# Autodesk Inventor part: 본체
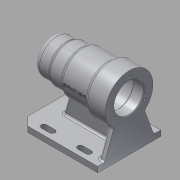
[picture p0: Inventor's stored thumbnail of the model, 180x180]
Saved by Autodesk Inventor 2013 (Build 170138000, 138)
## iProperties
Created: 2017-09
Part Number: 본체
Material: 알루미늄 6061
Document SubType Name: Modeling
Designer: Administrator
Density: 2.71 g/cm^3
Mass: 698.341 g
Surface Area: 709.394 cm^2
Volume: 257.691 cm^3
Author: Administrator
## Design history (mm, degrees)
sketch "스케치1"
  geometry: L1 (0, 0)-(-112, 0); L2 (-112, 22)-(-112, 34); L3 (-112, 34)-(-87, 34); L4 (-84, 31)-(-84, 30); L5 (-81.343, 30)-(-47.196, 30); L6 (-45, 30)-(-45, 30); L7 (-42, 27)-(-26.472, 27); L8 (-25, 27)-(-25, 28); L9 (-22, 25)-(-9, 25); L10 (0, 16)-(0, 0); L11 (-111, 21)-(-97, 21); L12 (-97, 21)-(-97, 21); L13 (-94, 24)-(-46, 24); L14 (-43, 21)-(-43, 21); L15 (-43, 21)-(-31.3, 21); L16 (-31, 20.7)-(-31, 17.5); L17 (-31, 17.5)-(-13.3, 17.5); L18 (-13, 17.2)-(-13, 16); L19 (-13, 16)-(-9.3, 16); L20 (-9, 15.7)-(-9, 10.5); L21 (-9, 10.5)-(-9, 10.5); L22 (-6, 7.5)-(-6, 0); L23 (-112, 22)-(-111, 21); A1 r 3 centre (-22, 28) between (-24.236, 26) and (-22, 25); A2 r 3 centre (-26.472, 24) between (-24.236, 26) and (-26.472, 27); A3 r 3 centre (-42, 30) between (-44.598, 28.5) and (-42, 27); A4 r 3 centre (-47.196, 27) between (-44.598, 28.5) and (-47.196, 30); A5 r 3 centre (-87, 31) between (-84.172, 32) and (-87, 34); A6 r 3 centre (-81.343, 33) between (-84.172, 32) and (-81.343, 30); A7 r 3 centre (-9, 7.5) between (-6, 7.5) and (-9, 10.5); A8 r 0.3 centre (-9.3, 15.7) between (-9, 15.7) and (-9.3, 16); A9 r 0.3 centre (-13.3, 17.2) between (-13, 17.2) and (-13.3, 17.5); A10 r 0.3 centre (-31.3, 20.7) between (-31, 20.7) and (-31.3, 21); A11 r 3 centre (-46, 21) between (-43, 21) and (-46, 24); A12 r 3 centre (-94, 21) between (-94, 24) and (-97, 21); A13 r 9 centre (-9, 16) between (0, 16) and (-9, 25); 9 further points
  constraints: 46 end point, 29 point on circle, 26 tangent, 23 point on line, 15 parallel, 13 centre point, 8 equal radius, 5 perpendicular, 1 collinear, 1 horizontal
  dimensions: "d0" = 112 distance of L1.start L1.end; "d1" = 25 distance of point (-25, 25) point (0, 25); "d2" = 45 distance between parallel lines of L6 L10; "d3" = 84 distance between parallel lines of L4 L10; "d4" = 50 diameter of L9 L1; "d5" = 54 diameter of L7 L1; "d6" = 60 diameter of L5 L1; "d7" = 68 diameter of L3 L1; "d8" = 3 radius of A1; "d9" = 3 radius of A5; "d10" = 42 diameter of L11 L1; "d11" = 48 diameter of L13 L1; "d12" = 42 diameter of L15 L1; "d13" = 35 diameter of L17 L1; "d14" = 32 diameter of L19 L1; "d16" = 21 diameter of L21 L1; "d17" = 15 distance of point (-112, 21) L11.end; "d18" = 54 distance of point (-97, 24) point (-43, 24); "d19" = 12 distance of L14.end point (-31, 21); "d20" = 18 distance of L16.end point (-13, 17.5); "d21" = 4 distance of L18.end point (-9, 16); "d22" = 3 distance of L20.end point (-6, 10.5); "d23" = 3 radius of A7; "d24" = 0.3 radius of A8; "d25" = 1 distance of L2.start point (-112, 21); "d26" = 1 distance of L11.start point (-112, 21) (= d25); "d27" = 9 radius of A13
revolve "회전1" sketch "스케치1" stored, may be unused: angle "d28" = 90 deg
node "작업 평면1"
sketch "스케치2"
  geometry: L1 (12, 45)-(112, 45); L2 (112, 45)-(112, -45); L3 (112, -45)-(12, -45); L4 (0, -33)-(0, 33); L5 (112, 34)-(112, -34) reference; L6 (12, 45)-(0, 33); L7 (0, -33)-(12, -45); 3 further points
  constraints: 12 end point, 4 point on line, 2 parallel, 1 horizontal, 1 perpendicular
  dimensions: "d30" = 0 distance between parallel lines of L2 L5; "d31" = 112 distance of point (0, 45) L1.end; "d32" = 90 distance of L1.end L2.end; "d33" = 45 distance from line of L1 point (0, 0); "d34" = 12 distance of L1.start point (0, 45); "d35" = 12 distance of L4.end point (0, 45) (= d34); "d36" = 12 distance of L4.start point (0, -45) (= d34); "d37" = 12 distance of L3.end point (0, -45) (= d36)
extrude "돌출1" join sketch "스케치2" distance "d38" = 8; taper "d39" = 0 deg
sketch "스케치3"
  geometry: L1 (62, -45)-(62, 45) reference; L2 (62, -35)-(26.008, -21.9); L3 (26.008, 21.9)-(62, 35); L4 (62, -35)-(62, 35); A1 r 34 centre (0, 0) between (26.008, -21.9) and (26.008, 21.9) reference; A2 r 34 centre (0, 0) between (26.008, -21.9) and (26.008, 21.9)
  constraints: 6 end point, 4 point on circle, 2 point on line, 1 centre point, 1 collinear, 1 concentric
  dimensions: "d40" = 10 distance of L1.start L2.start; "d41" = 10 distance of L1.end L3.end; "d42" = 110 deg angle of L2 L1; "d43" = 110 deg angle of L1 L3
extrude "돌출2" join sketch "스케치3" distance "d44" = 8; taper "d45" = 0 deg
sketch "스케치4"
  geometry: L1 (-12, -62)-(-112, -62) reference; L2 (-42, -27)-(-26.472, -27) reference; L3 (-81.343, -30)-(-47.196, -30) reference; L4 (-22, -62)-(-31.378, -27); L5 (0, -70)-(0, -62) reference; 1 further point
  constraints: 2 end point, 2 point on line
  dimensions: "d46" = 22 distance from line of L5 L4.start; "d47" = 105 deg angle of L1 L4
feature "리브1" sketch "스케치4" dims "d48" = 1, "d49" = 8, "d50" = 0, "d51" = 0, "d52" = 1, "d53" = 1
fillet "모깎기1" dims "d54" = 3
fillet "모깎기2" dims "d55" = 3
sketch "스케치5"
  geometry: L1 (112, 37.101)-(112, 45) reference; L2 (104, 7)-(104, 31.904) reference; L3 (24, 38)-(36, 38); L4 (24, 30)-(36, 30); L5 (76, 38)-(88, 38); L6 (76, 30)-(88, 30); A1 r 4 centre (24, 34) between (24, 38) and (24, 30); A2 r 4 centre (36, 34) between (36, 38) and (36, 30); A3 r 4 centre (76, 34) between (76, 38) and (76, 30); A4 r 4 centre (88, 34) between (88, 38) and (88, 30); 1 further point
  constraints: 8 end point, 8 point on circle, 4 centre point, 4 tangent, 3 parallel, 1 perpendicular
  dimensions: "d56" = 8 diameter of A1; "d58" = 8 diameter of A2; "d59" = 12 distance of A2.centre A1.centre; "d60" = 34 vertical distance of point (0, 0) A1.centre; "d61" = 12 distance of A4.centre A3.centre; "d62" = 8 diameter of A3; "d63" = 8 diameter of A4; "d64" = 34 vertical distance of point (0, 0) A3.centre; "d65" = 34 vertical distance of point (0, 0) A4.centre; "d66" = 34 vertical distance of point (0, 0) A2.centre; "d67" = 24 distance from line of L1 A4.centre; "d68" = 40 distance of A3.centre A2.centre
extrude "돌출3" cut sketch "스케치5" stored distance "d69" = 8; taper "d70" = 0 deg
sketch "스케치6" dims "d71" = 52
  geometry: C1 r 22 at (-70, 45) reference; A1 r 34 centre (-70, 45) between (-45.289, 68.353) and (-45.289, 21.647) reference; 2 further points
  constraints: 1 coincident, 1 horizontal alignment, 2 other
  dimensions: "d73" = 0 vertical distance of point (-96, 45) A1.centre
hole "구멍1" sketch "스케치6" at (-96, 45) diameter "d74" = 3.242; stored, may be unused: countersink angle "d78" = 90 deg, drill point angle "d80" = 118 deg; dims "d75" = 8, "d76" = 4, "d77" = 2, "d79" = 11
node "작업 평면2"
sketch "스케치7"
  geometry: L1 (47.408, 3.073)-(80.592, 3.073); L2 (80.592, 3.073)-(80.592, -3.073); L3 (80.592, -3.073)-(47.408, -3.073); L4 (47.408, -3.073)-(47.408, 3.073); L5 (64, 3.073)-(64, -3.073); L6 (47.408, 0)-(80.592, 0); L7 (112, 34)-(112, -24.711) reference; 1 further point
  constraints: 4 end point, 4 midpoint, 2 other
  dimensions: "d85" = 48 distance between parallel lines of L7 L5; "d86" = 0 distance from line of point (0, 0) L6
feature "엠보싱1" sketch "스케치7" dims "d87" = 0.5, "d88" = 0
node "솔리드1"
mirror "대칭1"
pattern_circular "원형 패턴1" dims angle "d82" = 360 deg
other parameters: "d84" = -34.5
